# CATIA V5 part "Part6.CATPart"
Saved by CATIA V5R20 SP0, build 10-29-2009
Part number: Part6
Bounding box of the stored display mesh (mm): x 236.096 to 267.846, y -59.935 to -28.185, z 12.7 to 50.927
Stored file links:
  C:\Users\TAK SYS\Desktop\Part6.CATPart
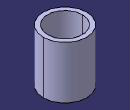
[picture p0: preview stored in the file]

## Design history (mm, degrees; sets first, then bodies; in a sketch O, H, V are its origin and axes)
Body1 (main body)
  DatumSurface1
  Sketch1 on face of DatumSurface1, origin (0, 0, 12.7), H (1, 0, 0), V (0, 1, 0)
    circle A1 centre (251.9715, -44.0598) radius 15.875
    circle A2 centre (251.9715, -44.0598) radius 12.7
    radius A1 = 15.875
    radius A2 = 12.7
  Pad1: profile Sketch1.A2, length 38.227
